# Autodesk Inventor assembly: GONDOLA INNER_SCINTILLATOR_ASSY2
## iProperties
Shininess: 64.0
Length Units: 11272
Angle Units: 11279
Time Units: 11290
Mass Units: 11286
Length Display Precision: 3
Angle Display Precision: 2
Compacted: True
Part Number: GONDOLA INNER_SCINTILLATOR_ASSY2
Document SubType Name: Assembly
Created: 2004-08
Designer: John Blackburn
Manufacturer: Standard
Standards Organization: Custom
Density: 0.0
Volumn: 0.0
Area: 0.0
PropertySet Name: Model Information
Control State: 0
Master: False
Checked Out: False
Author: John Blackburn
